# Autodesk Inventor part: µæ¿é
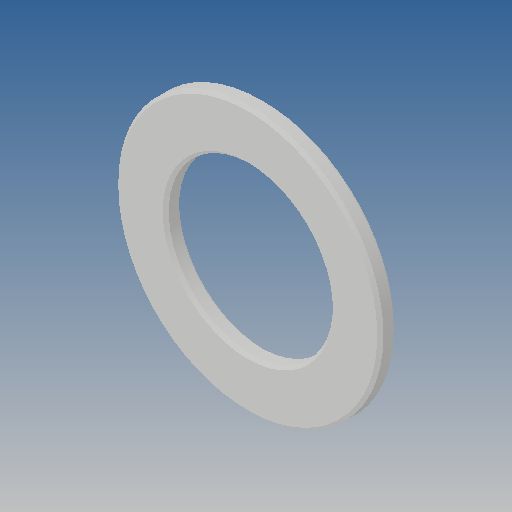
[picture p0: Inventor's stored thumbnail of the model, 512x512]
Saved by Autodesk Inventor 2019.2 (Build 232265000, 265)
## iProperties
Created: 2013-09
Part Number: µæ¿é
Material: Ogólny
Document SubType Name: Modeling
Designer: CADENGINEERING4
Density: 1 g/cm^3
Appearance: Domyślna
Author: CADENGINEERING4
Revision Number: ÈÎºÎ
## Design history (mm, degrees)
feature "µ¹½Ç1"
node "Bryła1"
